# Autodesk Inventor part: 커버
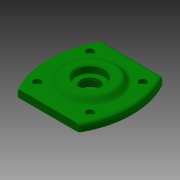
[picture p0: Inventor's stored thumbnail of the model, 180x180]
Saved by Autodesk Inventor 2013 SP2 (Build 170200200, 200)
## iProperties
Created: 2016-05
Part Number: 커버
Document SubType Name: Modeling
Designer: mduedu
Density: 2.71 g/cm^3
Material: 알루미늄 6061
Author: mduedu
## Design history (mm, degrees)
sketch "스케치1"
  geometry: L1 (0, 0)-(-37.029, 37.029); L2 (0, 0)-(0, 45); L3 (0, 0)-(45, 0); L4 (32.942, 45)-(-32.942, 45); L5 (32.942, -45)-(-32.942, -45); C1 r 25 at (0, 0); A1 r 90 centre (45, 0) between (-32.942, 45) and (-32.942, -45); A2 r 90 centre (-45, 0) between (32.942, -45) and (32.942, 45); 1 further point
  constraints: 10 end point, 6 point on circle, 3 centre point, 2 horizontal alignment, 2 parallel, 1 coincident, 1 horizontal, 1 midpoint, 2 other
  dimensions: "d28" = 90 distance between centres of A2 A1; "d30" = 50 diameter of C1; "d31" = 45 deg angle of L2 L1; "d36" = 45 distance from line of L2 A1.centre (= 0.5 x d28); "d37" = 90 distance between parallel lines of L4 L5
extrude "돌출1" new body sketch "스케치1" distance "d0" = 10; taper "d1" = 0 deg
extrude "돌출2" join sketch "스케치1" distance "d2" = 12; taper "d3" = 0 deg
sketch "스케치2"
  geometry: C1 r 30 at (0, 0); 1 further point
  constraints: 1 centre point, 1 coincident
  dimensions: "d4" = 60 diameter of C1
extrude "돌출3" join sketch "스케치2" distance "d5" = 5; taper "d6" = -45 deg
sketch "스케치3"
  geometry: C1 r 1.621 at (-28.284, 28.284) reference; C2 r 1.621 at (28.284, 28.284) reference; C3 r 1.621 at (28.284, -28.284) reference; C4 r 1.621 at (-28.284, -28.284) reference; 1 further point
hole "구멍1" sketch "스케치3" at (28.284, 28.284), (-28.284, 28.284), (-28.284, -28.284), (28.284, -28.284) diameter "d7" = 4.5; stored, may be unused: countersink angle "d11" = 90 deg, drill point angle "d13" = 118 deg; dims "d8" = 6, "d9" = 8, "d10" = 4.4, "d12" = 8
fillet "모깎기1" dims "d14" = 3
sketch "스케치4"
  geometry: L1 (-23.757, 15)-(23.757, 15) reference; L2 (25, -12)-(-25, -12) reference; L3 (0, -12)-(0, 15); L4 (-20, -12)-(-20, 0); L5 (-20, 0)-(-15, 0); L6 (-15, 0)-(-15, 3); L7 (-15, 3)-(-10, 3); L8 (-10, 3)-(-10, 7); L9 (-10, 7)-(-15, 7); L10 (-15, 7)-(-15, 15); 1 further point
  constraints: 16 end point, 6 parallel, 2 midpoint, 2 point on line, 1 perpendicular
  dimensions: "d15" = 40 diameter of L4 L3; "d16" = 30 diameter of L10 L3; "d17" = 8 distance of L9.end L10.end; "d18" = 12 distance of L4.start L4.end; "d19" = 3 distance of L5.end L6.end; "d20" = 30 diameter of L6 L3; "d21" = 20 diameter of L8 L3
revolve "회전1" sketch "스케치4" stored, may be unused: angle "d22" = 90 deg
fillet "모깎기2" dims "d23" = 3
fillet "모깎기3" dims "d24" = 0.3
chamfer "모따기1" distance "d25" = 1; stored, may be unused: second distance "d26" = 2, angle "d27" = 45 deg
node "솔리드1"
node "참조2"
node "참조3"
node "참조4"
node "참조5"
